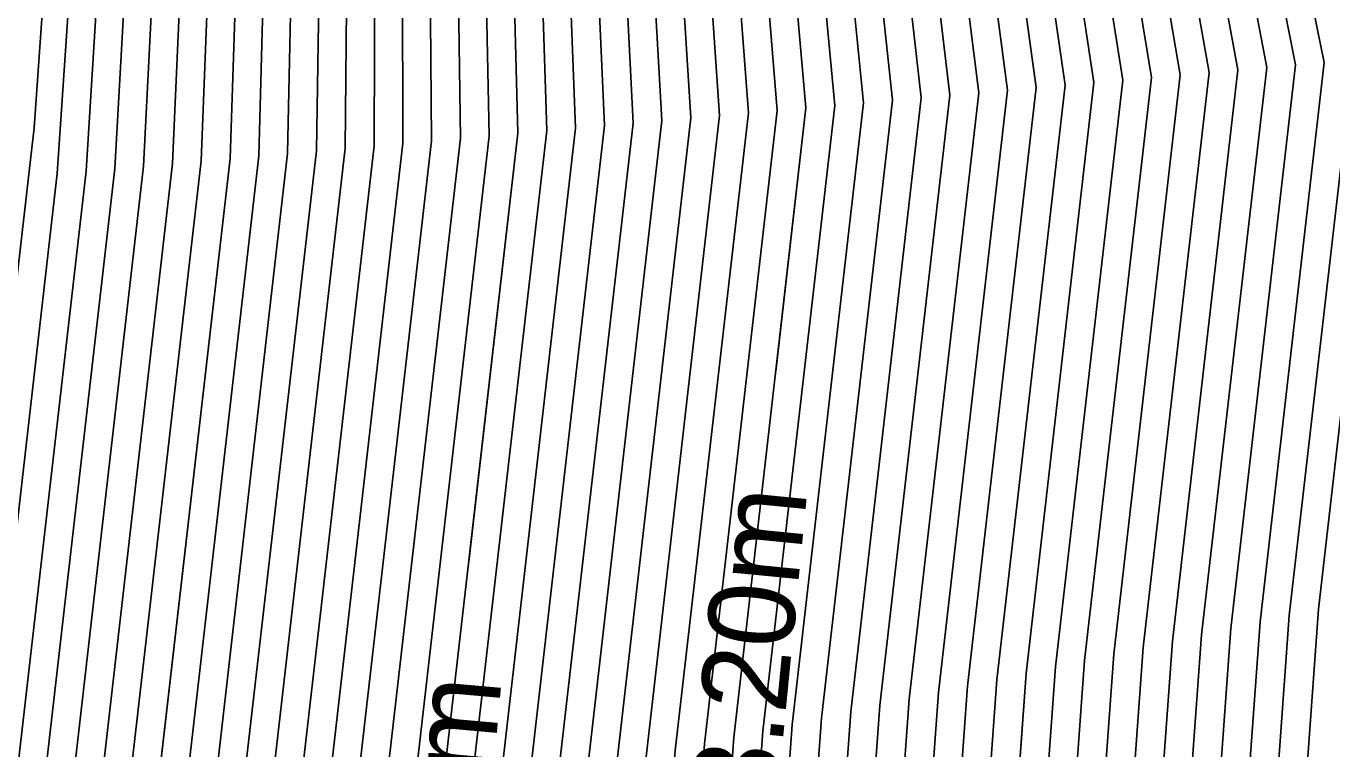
# Model space of a CAD drawing. Extents: x -866683 to -866410, y -1041951 to -1040252.
# Drawn here: x -866449.115 to -866444.577, y -1041930.934 to -1041928.421 of the extents above; entities that cross this region are included whole.
import ezdxf

# ---------------------------------------------------------------- set-up
doc = ezdxf.new("R2010")
doc.units = 0
for name, color, linetype in [('V-HL', 7, 'Continuous'), ('V-VEDL', 7, 'Continuous'), ('V_po_cm', 7, 'Continuous')]:
    doc.layers.add(name, color=color, linetype=linetype)

msp = doc.modelspace()

# ---------------------------------------------------------------- linework, layer by layer
at = {"layer": 'V-HL'}
msp.add_lwpolyline([(-866444.9217, -1041934.3497), (-866444.6048, -1041933.5435), (-866444.724, -1041932.9551), (-866444.7301, -1041931.9234), (-866444.6231, -1041930.4482), (-866444.4031, -1041928.5297), (-866444.4224, -1041928.4411)], dxfattribs=at)
at = {"layer": 'V-VEDL'}
for points in [[(-866449.7169, -1041924.4172), (-866449.1108, -1041924.2576), (-866448.5043, -1041924.4695), (-866447.5946, -1041924.9732), (-866446.3815, -1041925.7685), (-866445.6512, -1041926.9834), (-866445.4039, -1041928.6176), (-866445.6394, -1041930.6714), (-866445.7539, -1041932.2504), (-866445.7474, -1041933.3549), (-866445.6198, -1041933.9847), (-866446.0907, -1041935.3297), (-866447.16, -1041937.39), (-866450.4954, -1041942.9408)], [(-866450.4284, -1041941.6368), (-866447.8087, -1041937.2771), (-866446.9808, -1041935.6001), (-866446.6348, -1041934.426), (-866446.7708, -1041933.7547), (-866446.7777, -1041932.5775), (-866446.6557, -1041930.8945), (-866446.4047, -1041928.7056), (-866446.5506, -1041927.0409), (-866447.0935, -1041925.9004), (-866448.0334, -1041925.2842), (-866448.7383, -1041924.894), (-866449.2081, -1041924.7298), (-866449.6778, -1041924.8534)], [(-866450.3613, -1041940.3327), (-866448.4574, -1041937.1642), (-866447.8709, -1041935.8705), (-866447.6498, -1041934.8672), (-866447.7942, -1041934.1545), (-866447.8016, -1041932.9046), (-866447.672, -1041931.1176), (-866447.4055, -1041928.7935), (-866447.45, -1041927.0984), (-866447.8056, -1041926.0323), (-866448.4722, -1041925.5952), (-866448.9722, -1041925.3184), (-866449.3055, -1041925.2019), (-866449.6386, -1041925.2896)], [(-866449.5994, -1041925.7259), (-866449.4028, -1041925.6741), (-866449.2061, -1041925.7428), (-866448.9111, -1041925.9062), (-866448.5176, -1041926.1641), (-866448.3494, -1041927.1559), (-866448.4062, -1041928.8814), (-866448.6883, -1041931.3407), (-866448.8254, -1041933.2317), (-866448.8176, -1041934.5543), (-866448.6648, -1041935.3085), (-866448.761, -1041936.1408), (-866449.1061, -1041937.0514), (-866450.2943, -1041939.0287)]]:
    msp.add_lwpolyline(points, dxfattribs=at)
at = {"layer": 'V_po_cm'}
for points in [[(-866449.9375, -1041942.2799), (-866448.5659, -1041940.803), (-866446.5761, -1041937.4915), (-866445.2896, -1041935.0864), (-866444.7063, -1041933.5876), (-866444.8263, -1041932.9951), (-866444.8325, -1041931.9561), (-866444.7248, -1041930.4705), (-866444.5032, -1041928.5385), (-866444.8418, -1041926.9316), (-866445.7406, -1041925.6499), (-866447.1996, -1041924.6933), (-866448.2938, -1041924.0876), (-866449.0232, -1041923.8327), (-866449.3877, -1041923.9286)], [(-866449.9419, -1041942.1825), (-866448.595, -1041940.7321), (-866446.641, -1041937.4802), (-866445.3786, -1041935.1134), (-866444.8078, -1041933.6317), (-866444.9287, -1041933.0351), (-866444.9349, -1041931.9888), (-866444.8264, -1041930.4929), (-866444.6033, -1041928.5473), (-866444.9317, -1041926.9374), (-866445.8118, -1041925.6631), (-866447.2435, -1041924.7244), (-866448.3172, -1041924.13), (-866449.0329, -1041923.8799), (-866449.3906, -1041923.9741)], [(-866449.9463, -1041942.0851), (-866448.6241, -1041940.6613), (-866446.7059, -1041937.469), (-866445.4676, -1041935.1405), (-866444.9093, -1041933.6758), (-866445.031, -1041933.075), (-866445.0372, -1041932.0215), (-866444.928, -1041930.5152), (-866444.7033, -1041928.5561), (-866445.0217, -1041926.9431), (-866445.883, -1041925.6762), (-866447.2874, -1041924.7555), (-866448.3406, -1041924.1724), (-866449.0426, -1041923.9271), (-866449.3935, -1041924.0195)], [(-866449.9507, -1041941.9877), (-866448.6532, -1041940.5905), (-866446.7707, -1041937.4577), (-866445.5566, -1041935.1675), (-866445.0108, -1041933.72), (-866445.1333, -1041933.115), (-866445.1396, -1041932.0542), (-866445.0297, -1041930.5375), (-866444.8034, -1041928.5649), (-866445.1116, -1041926.9489), (-866445.9542, -1041925.6894), (-866447.3313, -1041924.7866), (-866448.364, -1041924.2149), (-866449.0524, -1041923.9743), (-866449.3964, -1041924.0649)], [(-866449.3993, -1041924.1103), (-866449.0621, -1041924.0215), (-866448.3874, -1041924.2573), (-866447.3752, -1041924.8177), (-866446.0254, -1041925.7026), (-866445.2016, -1041926.9546), (-866444.9035, -1041928.5737), (-866445.1313, -1041930.5598), (-866445.242, -1041932.0869), (-866445.2357, -1041933.155), (-866445.1123, -1041933.7641), (-866445.6456, -1041935.1945), (-866446.8356, -1041937.4464), (-866448.6823, -1041940.5196), (-866449.9551, -1041941.8903)], [(-866449.9596, -1041941.7928), (-866448.7114, -1041940.4488), (-866446.9005, -1041937.4351), (-866445.7346, -1041935.2216), (-866445.2138, -1041933.8082), (-866445.338, -1041933.195), (-866445.3444, -1041932.1196), (-866445.2329, -1041930.5821), (-866445.0036, -1041928.5825), (-866445.2915, -1041926.9604), (-866446.0966, -1041925.7158), (-866447.419, -1041924.8488), (-866448.4108, -1041924.2998), (-866449.0718, -1041924.0688), (-866449.4022, -1041924.1557)], [(-866449.4051, -1041924.2012), (-866449.0816, -1041924.116), (-866448.4342, -1041924.3422), (-866447.4629, -1041924.8799), (-866446.1679, -1041925.729), (-866445.3814, -1041926.9661), (-866445.1037, -1041928.5912), (-866445.3345, -1041930.6044), (-866445.4468, -1041932.1523), (-866445.4404, -1041933.235), (-866445.3153, -1041933.8523), (-866445.8236, -1041935.2486), (-866446.9654, -1041937.4238), (-866448.7404, -1041940.3779), (-866449.964, -1041941.6954)], [(-866449.9684, -1041941.598), (-866448.7695, -1041940.3071), (-866447.0302, -1041937.4125), (-866445.9127, -1041935.2757), (-866445.4168, -1041933.8965), (-866445.5427, -1041933.2749), (-866445.5492, -1041932.185), (-866445.4362, -1041930.6267), (-866445.2037, -1041928.6), (-866445.4714, -1041926.9719), (-866446.2391, -1041925.7422), (-866447.5068, -1041924.911), (-866448.4576, -1041924.3847), (-866449.0913, -1041924.1632), (-866449.408, -1041924.2466)], [(-866449.4109, -1041924.292), (-866449.101, -1041924.2104), (-866448.4809, -1041924.4271), (-866447.5507, -1041924.9421), (-866446.3103, -1041925.7554), (-866445.5613, -1041926.9776), (-866445.3038, -1041928.6088), (-866445.5378, -1041930.649), (-866445.6515, -1041932.2177), (-866445.645, -1041933.3149), (-866445.5183, -1041933.9406), (-866446.0017, -1041935.3027), (-866447.0951, -1041937.4012), (-866448.7986, -1041940.2362), (-866449.9728, -1041941.5006)], [(-866449.1205, -1041924.3048), (-866448.5277, -1041924.512), (-866447.6385, -1041925.0043), (-866446.4527, -1041925.7817), (-866445.7412, -1041926.9891), (-866445.504, -1041928.6264), (-866445.7411, -1041930.6937), (-866445.8563, -1041932.2832), (-866445.8497, -1041933.3949), (-866445.7213, -1041934.0288), (-866446.1797, -1041935.3568), (-866447.2248, -1041937.3787), (-866448.8568, -1041940.0945), (-866449.9816, -1041941.3058)], [(-866449.9861, -1041941.2084), (-866448.8859, -1041940.0237), (-866447.2897, -1041937.3674), (-866446.2687, -1041935.3838), (-866445.8228, -1041934.073), (-866445.9521, -1041933.4349), (-866445.9587, -1041932.3159), (-866445.8427, -1041930.716), (-866445.6041, -1041928.6352), (-866445.8311, -1041926.9949), (-866446.5239, -1041925.7949), (-866447.6823, -1041925.0354), (-866448.5511, -1041924.5544), (-866449.1302, -1041924.352)], [(-866449.14, -1041924.3993), (-866448.5745, -1041924.5969), (-866447.7262, -1041925.0665), (-866446.5951, -1041925.8081), (-866445.9211, -1041927.0006), (-866445.7041, -1041928.644), (-866445.9443, -1041930.7383), (-866446.0611, -1041932.3486), (-866446.0544, -1041933.4748), (-866445.9243, -1041934.1171), (-866446.3577, -1041935.4108), (-866447.3546, -1041937.3561), (-866448.9149, -1041939.9529), (-866449.9905, -1041941.111)], [(-866449.9949, -1041941.0136), (-866448.944, -1041939.882), (-866447.4195, -1041937.3448), (-866446.4467, -1041935.4379), (-866446.0258, -1041934.1612), (-866446.1567, -1041933.5148), (-866446.1634, -1041932.3813), (-866446.0459, -1041930.7606), (-866445.8042, -1041928.6528), (-866446.011, -1041927.0064), (-866446.6663, -1041925.8213), (-866447.7701, -1041925.0976), (-866448.5979, -1041924.6393), (-866449.1497, -1041924.4465)], [(-866449.1594, -1041924.4937), (-866448.6213, -1041924.6818), (-866447.814, -1041925.1287), (-866446.7375, -1041925.8345), (-866446.1009, -1041927.0121), (-866445.9043, -1041928.6616), (-866446.1476, -1041930.7829), (-866446.2658, -1041932.414), (-866446.2591, -1041933.5548), (-866446.1273, -1041934.2053), (-866446.5357, -1041935.4649), (-866447.4843, -1041937.3335), (-866448.9731, -1041939.8112), (-866449.9993, -1041940.9162)], [(-866449.1692, -1041924.5409), (-866448.6447, -1041924.7242), (-866447.8579, -1041925.1598), (-866446.8087, -1041925.8477), (-866446.1909, -1041927.0179), (-866446.0044, -1041928.6704), (-866446.2492, -1041930.8052), (-866446.3682, -1041932.4467), (-866446.3614, -1041933.5948), (-866446.2288, -1041934.2495), (-866446.6247, -1041935.492), (-866447.5492, -1041937.3222), (-866449.0022, -1041939.7403), (-866450.0037, -1041940.8188)], [(-866449.1789, -1041924.5881), (-866448.6681, -1041924.7666), (-866447.9018, -1041925.1909), (-866446.8799, -1041925.8608), (-866446.2808, -1041927.0236), (-866446.1044, -1041928.6792), (-866446.3508, -1041930.8275), (-866446.4706, -1041932.4794), (-866446.4638, -1041933.6348), (-866446.3303, -1041934.2936), (-866446.7138, -1041935.519), (-866447.6141, -1041937.3109), (-866449.0313, -1041939.6695), (-866450.0081, -1041940.7214)], [(-866449.1886, -1041924.6353), (-866448.6915, -1041924.8091), (-866447.9456, -1041925.222), (-866446.9511, -1041925.874), (-866446.3707, -1041927.0294), (-866446.2045, -1041928.688), (-866446.4525, -1041930.8499), (-866446.573, -1041932.5121), (-866446.5661, -1041933.6747), (-866446.4318, -1041934.3377), (-866446.8028, -1041935.546), (-866447.6789, -1041937.2997), (-866449.0604, -1041939.5986), (-866450.0125, -1041940.6239)], [(-866449.1984, -1041924.6826), (-866448.7149, -1041924.8515), (-866447.9895, -1041925.2531), (-866447.0223, -1041925.8872), (-866446.4607, -1041927.0351), (-866446.3046, -1041928.6968), (-866446.5541, -1041930.8722), (-866446.6754, -1041932.5448), (-866446.6684, -1041933.7147), (-866446.5333, -1041934.3818), (-866446.8918, -1041935.5731), (-866447.7438, -1041937.2884), (-866449.0895, -1041939.5278), (-866450.017, -1041940.5265)], [(-866449.1476, -1041939.3861), (-866447.8736, -1041937.2658), (-866447.0698, -1041935.6271), (-866446.7363, -1041934.4701), (-866446.8731, -1041933.7947), (-866446.8801, -1041932.6102), (-866446.7573, -1041930.9168), (-866446.5048, -1041928.7143), (-866446.6406, -1041927.0466), (-866447.1647, -1041925.9136), (-866448.0773, -1041925.3153), (-866448.7617, -1041924.9364), (-866449.2179, -1041924.777)], [(-866449.1767, -1041939.3152), (-866447.9384, -1041937.2545), (-866447.1588, -1041935.6542), (-866446.8378, -1041934.5142), (-866446.9755, -1041933.8347), (-866446.9825, -1041932.6429), (-866446.859, -1041930.9391), (-866446.6048, -1041928.7231), (-866446.7305, -1041927.0524), (-866447.2359, -1041925.9268), (-866448.1212, -1041925.3464), (-866448.7851, -1041924.9789), (-866449.2276, -1041924.8242)], [(-866449.2058, -1041939.2444), (-866448.0033, -1041937.2432), (-866447.2478, -1041935.6812), (-866446.9393, -1041934.5583), (-866447.0778, -1041933.8746), (-866447.0849, -1041932.6757), (-866446.9606, -1041930.9614), (-866446.7049, -1041928.7319), (-866446.8204, -1041927.0581), (-866447.3071, -1041925.94), (-866448.1651, -1041925.3775), (-866448.8085, -1041925.0213), (-866449.2373, -1041924.8714)], [(-866449.2349, -1041939.1736), (-866448.0682, -1041937.2319), (-866447.3368, -1041935.7082), (-866447.0408, -1041934.6025), (-866447.1801, -1041933.9146), (-866447.1873, -1041932.7084), (-866447.0622, -1041930.9837), (-866446.805, -1041928.7407), (-866446.9104, -1041927.0639), (-866447.3783, -1041925.9531), (-866448.2089, -1041925.4086), (-866448.8318, -1041925.0637), (-866449.2471, -1041924.9186)], [(-866449.2568, -1041924.9659), (-866448.8552, -1041925.1062), (-866448.2528, -1041925.4397), (-866447.4496, -1041925.9663), (-866447.0003, -1041927.0696), (-866446.9051, -1041928.7495), (-866447.1639, -1041931.0061), (-866447.2897, -1041932.7411), (-866447.2825, -1041933.9546), (-866447.1423, -1041934.6466), (-866447.4258, -1041935.7353), (-866448.133, -1041937.2207), (-866449.264, -1041939.1027)], [(-866449.293, -1041939.0319), (-866448.1979, -1041937.2094), (-866447.5148, -1041935.7623), (-866447.2438, -1041934.6907), (-866447.3848, -1041933.9946), (-866447.392, -1041932.7738), (-866447.2655, -1041931.0284), (-866447.0051, -1041928.7583), (-866447.0902, -1041927.0754), (-866447.5208, -1041925.9795), (-866448.2967, -1041925.4708), (-866448.8786, -1041925.1486), (-866449.2665, -1041925.0131)], [(-866449.2763, -1041925.0603), (-866448.902, -1041925.1911), (-866448.3406, -1041925.5019), (-866447.592, -1041925.9927), (-866447.1802, -1041927.0811), (-866447.1052, -1041928.7671), (-866447.3671, -1041931.0507), (-866447.4944, -1041932.8065), (-866447.4872, -1041934.0345), (-866447.3453, -1041934.7348), (-866447.6039, -1041935.7894), (-866448.2628, -1041937.1981), (-866449.3221, -1041938.961)], [(-866449.3512, -1041938.8902), (-866448.3277, -1041937.1868), (-866447.6929, -1041935.8164), (-866447.4468, -1041934.779), (-866447.5895, -1041934.0745), (-866447.5968, -1041932.8392), (-866447.4687, -1041931.073), (-866447.2053, -1041928.7759), (-866447.2701, -1041927.0869), (-866447.6632, -1041926.0059), (-866448.3845, -1041925.533), (-866448.9254, -1041925.2335), (-866449.286, -1041925.1075)], [(-866449.2957, -1041925.1547), (-866448.9488, -1041925.276), (-866448.4284, -1041925.5641), (-866447.7344, -1041926.0191), (-866447.3601, -1041927.0926), (-866447.3054, -1041928.7847), (-866447.5704, -1041931.0953), (-866447.6992, -1041932.8719), (-866447.6918, -1041934.1145), (-866447.5483, -1041934.8231), (-866447.7819, -1041935.8434), (-866448.3925, -1041937.1755), (-866449.3803, -1041938.8193)], [(-866449.3152, -1041925.2491), (-866448.9956, -1041925.3608), (-866448.5161, -1041925.6263), (-866447.8768, -1041926.0454), (-866447.5399, -1041927.1041), (-866447.5055, -1041928.8023), (-866447.7736, -1041931.1399), (-866447.904, -1041932.9373), (-866447.8965, -1041934.1945), (-866447.7513, -1041934.9114), (-866447.9599, -1041935.8975), (-866448.5223, -1041937.1529), (-866449.4385, -1041938.6776)], [(-866449.4675, -1041938.6068), (-866448.5872, -1041937.1417), (-866448.0489, -1041935.9245), (-866447.8528, -1041934.9555), (-866447.9989, -1041934.2344), (-866448.0063, -1041932.97), (-866447.8753, -1041931.1622), (-866447.6056, -1041928.8111), (-866447.6299, -1041927.1099), (-866447.948, -1041926.0586), (-866448.56, -1041925.6574), (-866449.019, -1041925.4033), (-866449.3249, -1041925.2964)], [(-866449.4966, -1041938.5359), (-866448.652, -1041937.1304), (-866448.1379, -1041935.9516), (-866447.9543, -1041934.9996), (-866448.1012, -1041934.2744), (-866448.1087, -1041933.0027), (-866447.9769, -1041931.1846), (-866447.7057, -1041928.8199), (-866447.7198, -1041927.1156), (-866448.0192, -1041926.0718), (-866448.6039, -1041925.6885), (-866449.0424, -1041925.4457), (-866449.3347, -1041925.3436)], [(-866449.5257, -1041938.4651), (-866448.7169, -1041937.1191), (-866448.2269, -1041935.9786), (-866448.0558, -1041935.0437), (-866448.2035, -1041934.3144), (-866448.2111, -1041933.0355), (-866448.0785, -1041931.2069), (-866447.8058, -1041928.8287), (-866447.8097, -1041927.1214), (-866448.0904, -1041926.085), (-866448.6478, -1041925.7196), (-866449.0658, -1041925.4882), (-866449.3444, -1041925.3908)], [(-866449.3541, -1041925.438), (-866449.0892, -1041925.5306), (-866448.6917, -1041925.7507), (-866448.1616, -1041926.0982), (-866447.8997, -1041927.1271), (-866447.9059, -1041928.8374), (-866448.1801, -1041931.2292), (-866448.3135, -1041933.0682), (-866448.3059, -1041934.3544), (-866448.1573, -1041935.0879), (-866448.3159, -1041936.0057), (-866448.7818, -1041937.1078), (-866449.5548, -1041938.3943)], [(-866449.5839, -1041938.3234), (-866448.8466, -1041937.0965), (-866448.405, -1041936.0327), (-866448.2588, -1041935.132), (-866448.4082, -1041934.3944), (-866448.4159, -1041933.1009), (-866448.2818, -1041931.2515), (-866448.0059, -1041928.8462), (-866447.9896, -1041927.1329), (-866448.2328, -1041926.1114), (-866448.7355, -1041925.7818), (-866449.1126, -1041925.5731), (-866449.3639, -1041925.4852)], [(-866449.613, -1041938.2526), (-866448.9115, -1041937.0852), (-866448.494, -1041936.0597), (-866448.3603, -1041935.1761), (-866448.5106, -1041934.4343), (-866448.5183, -1041933.1336), (-866448.3834, -1041931.2738), (-866448.106, -1041928.855), (-866448.0795, -1041927.1386), (-866448.304, -1041926.1246), (-866448.7794, -1041925.8129), (-866449.136, -1041925.6155)], [(-866449.642, -1041938.1817), (-866448.9764, -1041937.0739), (-866448.583, -1041936.0868), (-866448.4618, -1041935.2202), (-866448.6129, -1041934.4743), (-866448.6206, -1041933.1663), (-866448.485, -1041931.2961), (-866448.2061, -1041928.8638), (-866448.1695, -1041927.1444), (-866448.3752, -1041926.1377), (-866448.8233, -1041925.844), (-866449.1594, -1041925.6579)], [(-866449.6711, -1041938.1109), (-866449.0413, -1041937.0626), (-866448.672, -1041936.1138), (-866448.5633, -1041935.2644), (-866448.7152, -1041934.5143), (-866448.723, -1041933.199), (-866448.5867, -1041931.3184), (-866448.3062, -1041928.8726), (-866448.2594, -1041927.1501), (-866448.4464, -1041926.1509), (-866448.8672, -1041925.8751), (-866449.1827, -1041925.7004)], [(-866446.5098, -1041929.6225), (-866446.4047, -1041928.7056), (-866446.5506, -1041927.0409), (-866447.0935, -1041925.9004), (-866447.3769, -1041925.7146)], [(-866449.171, -1041937.0401), (-866448.85, -1041936.1679), (-866448.7663, -1041935.3526), (-866448.9199, -1041934.5943), (-866448.9278, -1041933.2644), (-866448.7899, -1041931.3631), (-866448.5063, -1041928.8902), (-866448.4393, -1041927.1616), (-866448.5888, -1041926.1773), (-866448.955, -1041925.9373), (-866449.2295, -1041925.7853)], [(-866449.2359, -1041937.0288), (-866448.939, -1041936.1949), (-866448.8678, -1041935.3967), (-866449.0223, -1041934.6342), (-866449.0302, -1041933.2971), (-866448.8915, -1041931.3854), (-866448.6064, -1041928.899), (-866448.5292, -1041927.1674), (-866448.6601, -1041926.1905), (-866448.9988, -1041925.9684), (-866449.2529, -1041925.8277)], [(-866449.2763, -1041925.8702), (-866449.0427, -1041925.9995), (-866448.7313, -1041926.2037), (-866448.6192, -1041927.1731), (-866448.7065, -1041928.9078), (-866448.9932, -1041931.4077), (-866449.1325, -1041933.3298)], [(-866449.2997, -1041925.9126), (-866449.0866, -1041926.0306), (-866448.8025, -1041926.2169), (-866448.7091, -1041927.1789), (-866448.8066, -1041928.9166), (-866449.0948, -1041931.43), (-866449.2349, -1041933.3625)], [(-866449.1305, -1041926.0617), (-866448.8737, -1041926.2301), (-866448.799, -1041927.1846), (-866448.9066, -1041928.9254), (-866449.1964, -1041931.4523)], [(-866449.2981, -1041931.4746), (-866449.0067, -1041928.9342), (-866448.889, -1041927.1904), (-866448.9449, -1041926.2432), (-866449.1744, -1041926.0928)], [(-866447.7519, -1041926.1933), (-866447.45, -1041927.0984), (-866447.4055, -1041928.7935), (-866447.5764, -1041930.2839)], [(-866448.6839, -1041931.3027), (-866448.4062, -1041928.8814), (-866448.3539, -1041927.2924)], [(-866445.7048, -1041931.5729), (-866445.6394, -1041930.6714), (-866445.4039, -1041928.6176), (-866445.5828, -1041927.4354)], [(-866444.422, -1041928.4429), (-866444.4031, -1041928.5297), (-866444.6231, -1041930.4482), (-866444.7301, -1041931.9234), (-866444.7263, -1041932.5699)]]:
    msp.add_lwpolyline(points, dxfattribs=at)
msp.add_lwpolyline([(-866449.4204, -1041925.9913), (-866449.0161, -1041926.2564), (-866448.9725, -1041927.1401), (-866449.0875, -1041928.775), (-866449.3612, -1041931.161), (-866449.6024, -1041931.9084), (-866449.8112, -1041931.0171), (-866449.9875, -1041928.4872), (-866450.0394, -1041926.8088), (-866449.9666, -1041925.9819), (-866449.7693, -1041926.0066), (-866449.6209, -1041926.0186), (-866449.5215, -1041926.0179)], close=True, dxfattribs=at)

# ---------------------------------------------------------------- texts
for s, rotation, p in [('533.20m', 84.3928, (-866446.5526, -1041931.5927)), ('533.30m', 84.896, (-866447.6014, -1041932.2504))]:
    msp.add_text(s, height=0.3, rotation=rotation, dxfattribs=at).set_placement(p)

doc.saveas('drawing.dxf')
